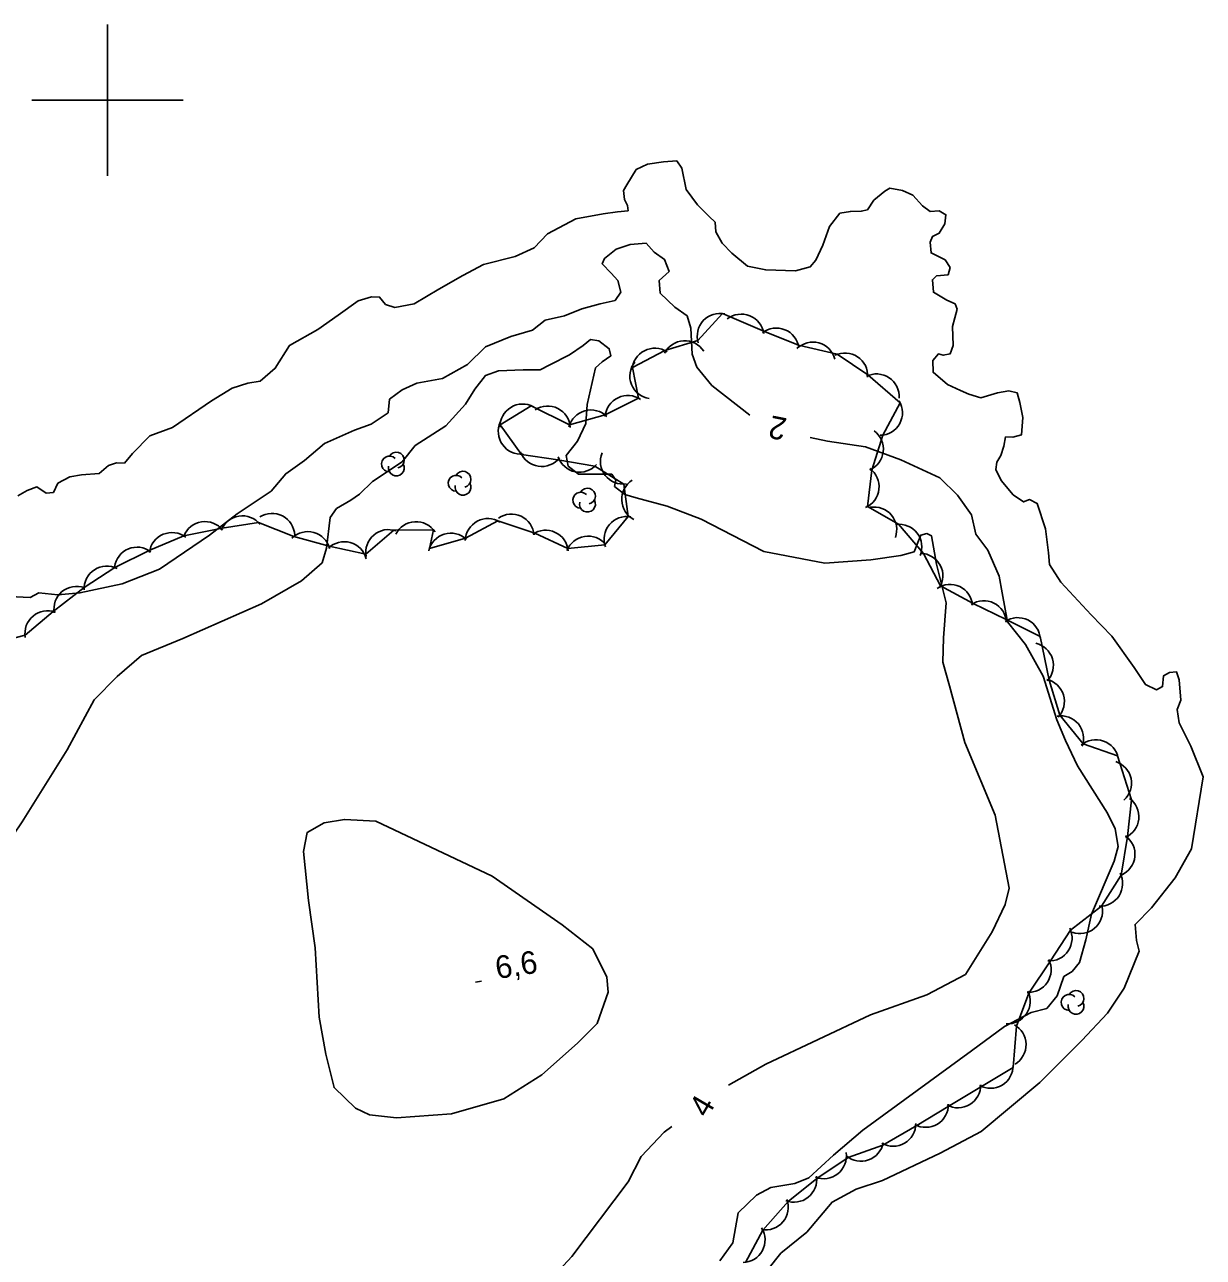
# Model space of a CAD drawing. Extents: x 643342 to 646936, y 5873857 to 5876103.
# Drawn here: x 644389 to 644544.9, y 5874247 to 5874410 of the extents above; entities that cross this region are included whole.
import ezdxf

# ---------------------------------------------------------------- set-up
doc = ezdxf.new("R2010")
doc.units = 0
for name, color, linetype in [('Niveau 2', 7, 'Continuous'), ('Niveau 3', 7, 'Continuous'), ('Niveau 4', 7, 'Continuous'), ('Niveau 44', 7, 'Continuous'), ('Niveau 61', 7, 'Continuous')]:
    doc.layers.add(name, color=color, linetype=linetype)

msp = doc.modelspace()

# ---------------------------------------------------------------- linework, layer by layer
at = {"layer": 'Niveau 2'}
for points in [[(644387.02, 5874334.38), (644389.75, 5874334.26), (644390.89, 5874334.84), (644393.4, 5874334.58), (644396.34, 5874334.84), (644401.93, 5874336.03), (644406.86, 5874338), (644413.47, 5874342.5), (644417.14, 5874345.31), (644421.62, 5874348.31), (644423.56, 5874350.61), (644426.02, 5874352.37), (644428.67, 5874354.62), (644432.67, 5874356.39), (644434.86, 5874357.17), (644437.1, 5874358.68), (644437.3, 5874360.47), (644438.98, 5874361.69), (644440.92, 5874362.57), (644444.3, 5874363.22), (644447.58, 5874365.05), (644449.99, 5874367.39), (644453.31, 5874368.75), (644456.2, 5874369.59), (644457.87, 5874370.93), (644460.43, 5874371.5), (644462.72, 5874372.42), (644465.15, 5874373.1), (644467.13, 5874373.51), (644467.86, 5874374.64), (644467.5, 5874376.16), (644466.59, 5874377.15), (644465.42, 5874378.35), (644465.71, 5874379.09), (644467.27, 5874380.29), (644469.11, 5874380.93), (644471.23, 5874381.11), (644472.28, 5874379.9), (644473.66, 5874378.95), (644474.27, 5874377.34), (644472.95, 5874376.15), (644473.09, 5874374.5), (644475.02, 5874372.65), (644476.66, 5874371.49), (644477.15, 5874369.87), (644477.32, 5874366.44), (644477.94, 5874364.71), (644479.92, 5874362.27), (644484.94, 5874358.34)], [(644428.94, 5874340.77), (644429.42, 5874344.84), (644430.27, 5874345.99), (644432.19, 5874347.1), (644433.3, 5874347.91), (644435.05, 5874349.6), (644438.97, 5874352.19), (644440.68, 5874354.36), (644444.72, 5874356.96), (644447.32, 5874359.79), (644448.57, 5874361.8), (644449.96, 5874363.58), (644451.68, 5874364.2), (644454.98, 5874364.37), (644457.23, 5874364.33), (644458.47, 5874365.03), (644461.09, 5874366.32), (644462.88, 5874367.55), (644463.87, 5874368.34), (644464.95, 5874368.2), (644466.34, 5874367.13), (644466.54, 5874366.2), (644465.42, 5874365.39), (644464.54, 5874364.61), (644463.41, 5874359.77), (644463.27, 5874357.26), (644462.16, 5874354.92), (644460.67, 5874353.01), (644460.9, 5874351.61), (644462.29, 5874350.54), (644466.67, 5874350.57), (644467.21, 5874349.78), (644467.04, 5874348.94), (644468.43, 5874347.87), (644469.89, 5874347.41), (644474, 5874346.34), (644478.52, 5874344.6), (644486.8, 5874340.34), (644494.85, 5874338.79), (644500.96, 5874339.2), (644504.93, 5874339.78), (644506.66, 5874340.29), (644507.15, 5874341.52), (644507.54, 5874342.5), (644508.36, 5874342.69), (644508.97, 5874342.39), (644509.64, 5874338.65), (644510.89, 5874333.55), (644510.57, 5874328.9), (644510.48, 5874325.7)], [(644492.92, 5874355.42), (644495.22, 5874354.93), (644500.26, 5874354.18), (644504.9, 5874352.45), (644510.07, 5874350.05), (644512.4, 5874347.76), (644514.27, 5874345.19), (644514.84, 5874342.63), (644516.44, 5874340.51), (644517.91, 5874337.08), (644518.33, 5874334.86), (644519, 5874331.01), (644521.38, 5874328.01), (644523.75, 5874323.83), (644525.53, 5874318.05), (644526.7, 5874315.31), (644528.28, 5874312), (644532.24, 5874305.71), (644533.24, 5874303.66), (644533.67, 5874301.33), (644533.12, 5874299.38), (644530.15, 5874292.37), (644529.37, 5874288.98), (644528.56, 5874285.95), (644527.59, 5874284.8), (644526.47, 5874284.11), (644525.61, 5874281.55), (644524.21, 5874279.88), (644522.13, 5874279.35), (644518.62, 5874277.5), (644514.27, 5874274.28), (644499.89, 5874263.79), (644496.02, 5874260.49), (644492.73, 5874257.48), (644490.9, 5874256.72), (644487.74, 5874256.21), (644485.82, 5874255.22), (644483.41, 5874252.87), (644482.68, 5874248.9), (644480.99, 5874246.5)], [(644325.11, 5874240.44), (644333.62, 5874247.45), (644341.01, 5874253.66), (644347.4, 5874260.49), (644360.4, 5874271.68), (644375.22, 5874286.59), (644382.72, 5874295.76), (644388.71, 5874304.58), (644394.65, 5874314.1), (644398.23, 5874320.69), (644401.28, 5874323.8), (644404.47, 5874326.56), (644409.96, 5874328.82), (644420.34, 5874333.39), (644425.64, 5874336.46), (644428.39, 5874338.83), (644428.94, 5874340.77)], [(644510.48, 5874325.7), (644511.34, 5874322.57), (644513.38, 5874315.05), (644517.37, 5874305.45), (644519.24, 5874295.79), (644518.72, 5874293.62), (644517.01, 5874290.03), (644513.46, 5874284.4), (644508.37, 5874281.71), (644500.91, 5874279.05), (644487.05, 5874272.52), (644482.14, 5874269.75)], [(644428.88, 5874273.83), (644427.99, 5874278.72), (644427.46, 5874287.89), (644426.57, 5874294.19), (644425.91, 5874300.64), (644426.4, 5874303.17), (644428.66, 5874304.43), (644431.33, 5874304.89), (644435.48, 5874304.66), (644450.85, 5874297.37), (644460.13, 5874290.96), (644464.17, 5874287.77), (644466.02, 5874284.03), (644466.19, 5874282.04), (644464.76, 5874277.9), (644462.15, 5874275.3), (644457.43, 5874271.11), (644452.39, 5874267.96), (644445.48, 5874265.94), (644438.2, 5874265.42), (644434.63, 5874265.82), (644432.78, 5874266.72), (644429.96, 5874269.43), (644428.88, 5874273.83)], [(644474.63, 5874264.29), (644473.62, 5874263.54), (644470.58, 5874260.32), (644468.86, 5874256.98), (644461.42, 5874247.1), (644449.83, 5874234.62)]]:
    msp.add_lwpolyline(points, dxfattribs=at)
at = {"layer": 'Niveau 3'}
msp.add_line((644448.67, 5874283.36), (644449.46, 5874283.48), dxfattribs=at)
at = {"layer": 'Niveau 4'}
for points in [[(644503.45, 5874388.38), (644502.78, 5874387.97), (644501.34, 5874386.77), (644500.49, 5874385.51), (644499.68, 5874385.32), (644498.25, 5874385.31), (644496.85, 5874385.07), (644495.46, 5874383.29), (644494.6, 5874380.83), (644493.69, 5874378.85), (644492.94, 5874377.96), (644490.97, 5874377.43), (644487.04, 5874377.56), (644484.63, 5874378.07), (644482.58, 5874379.79), (644481.29, 5874381.11), (644480.45, 5874382.58), (644480.34, 5874383.88), (644479.57, 5874384.65), (644478.02, 5874386.18), (644476.54, 5874388.19), (644475.95, 5874391), (644475.27, 5874392.01), (644473.51, 5874391.85), (644471.4, 5874391.55), (644469.91, 5874390.83), (644468.66, 5874388.82), (644468.25, 5874388.07), (644468.35, 5874386.89), (644468.77, 5874386.09), (644468.83, 5874385.38), (644467.42, 5874385.26), (644465.54, 5874384.98), (644461.92, 5874384.31), (644458.17, 5874382.32), (644456.42, 5874380.5), (644453.91, 5874379.33), (644449.73, 5874378.26), (644447, 5874376.83), (644443.83, 5874375.01), (644440.56, 5874373.06), (644437.99, 5874372.6), (644436.77, 5874372.97), (644435.97, 5874373.97), (644434.9, 5874374), (644433.16, 5874373.49), (644430.48, 5874371.59), (644427.79, 5874369.69), (644424.05, 5874367.58), (644422.17, 5874364.57), (644420.18, 5874362.85), (644418.54, 5874362.59), (644416.46, 5874361.93), (644413.75, 5874360.27), (644408.59, 5874356.73), (644405.6, 5874355.64), (644403.31, 5874353.3), (644402.23, 5874352.02), (644401.16, 5874352.04), (644400.12, 5874351.71), (644398.9, 5874350.66), (644396.55, 5874350.45), (644395.02, 5874350.2), (644393.43, 5874349.35), (644392.83, 5874348.11)], [(644541.45, 5874319.42), (644541.94, 5874320.65), (644541.72, 5874323.36), (644541.39, 5874324.4), (644540.45, 5874324.32), (644539.66, 5874323.9), (644539.54, 5874322.46), (644538.74, 5874322.03), (644537.26, 5874322.74), (644535.77, 5874324.98), (644532.82, 5874329.12), (644530.1, 5874331.97), (644526.06, 5874336.26), (644524.56, 5874338.62), (644524.44, 5874340.15), (644524.05, 5874343.33), (644522.94, 5874346.68), (644521.95, 5874347.19), (644521.15, 5874346.88), (644519.77, 5874347.83), (644518.19, 5874349.71), (644517.47, 5874351.19), (644517.63, 5874352.16), (644518.15, 5874353.04), (644518.52, 5874354.26), (644518.77, 5874355.47), (644519.72, 5874355.43), (644520.88, 5874355.77), (644521.05, 5874358.04), (644520.65, 5874360.03), (644520.3, 5874361.3), (644519.21, 5874361.57), (644517.69, 5874361.32), (644515.49, 5874360.65), (644513.92, 5874361.11), (644512.81, 5874361.61), (644511.08, 5874362.41), (644509.17, 5874364.02), (644509.16, 5874365.57), (644509.91, 5874366.47), (644510.52, 5874366.28), (644511.45, 5874366.48), (644511.83, 5874367.58), (644511.74, 5874370.07), (644512.38, 5874372.39), (644512.09, 5874373.08), (644510.98, 5874373.57), (644509.23, 5874374.61), (644509.09, 5874376.26), (644509.64, 5874376.79), (644511.17, 5874376.92), (644511.45, 5874377.9), (644510.77, 5874378.91), (644508.91, 5874379.82), (644508.8, 5874381.23), (644509.09, 5874381.97), (644510, 5874382.41), (644510.73, 5874383.66), (644510.87, 5874384.86), (644509.99, 5874385.38), (644508.81, 5874385.28), (644507.8, 5874386.02), (644506.5, 5874387.46), (644505.14, 5874388.05), (644503.45, 5874388.38)], [(644392.83, 5874348.11), (644391.89, 5874348.03), (644390.63, 5874348.87), (644389.36, 5874348.4), (644388.12, 5874347.7)], [(644487.34, 5874245.37), (644489.05, 5874247.53), (644492.49, 5874250.32), (644495.83, 5874254.29), (644499.01, 5874255.99), (644502.47, 5874257.12), (644510.1, 5874260.75), (644515.55, 5874263.6), (644523.3, 5874270.09), (644528.87, 5874275.67), (644532.24, 5874279.29), (644534.46, 5874282.57), (644536.42, 5874287.48), (644536.06, 5874288.88), (644535.89, 5874291), (644538.07, 5874293.2), (644541.18, 5874297.15), (644543.34, 5874301.02), (644544.92, 5874310.54), (644543.27, 5874314.59), (644541.72, 5874317.66), (644541.45, 5874319.42)]]:
    msp.add_lwpolyline(points, dxfattribs=at)
at = {"layer": 'Niveau 44'}
for points in [[(644484.36, 5874246.31), (644486.64, 5874250.59), (644489.99, 5874254.38), (644493.79, 5874257.4), (644497.94, 5874260.2), (644502.51, 5874261.83), (644507.03, 5874264.41), (644511.18, 5874266.91), (644515.59, 5874269.57), (644519.75, 5874272.07), (644520.2, 5874277.56), (644521.84, 5874281.9), (644524.69, 5874286.18), (644527.37, 5874290.23), (644531.44, 5874293.42), (644534.04, 5874297.52), (644534.91, 5874302.65), (644535.41, 5874307.48), (644533.59, 5874313.29), (644529.01, 5874314.89), (644525.94, 5874318.67), (644524.53, 5874323.32), (644523.33, 5874329.08), (644518.85, 5874331.31), (644514.5, 5874333.46), (644510.18, 5874335.78), (644507.89, 5874340.06), (644504.61, 5874343.92), (644500.52, 5874346.28), (644501.06, 5874351.1), (644502.51, 5874355.72), (644504.84, 5874359.97), (644500.53, 5874363.71), (644496.49, 5874366.4), (644491.37, 5874367.62), (644486.86, 5874369.41), (644481.34, 5874371.8), (644478.05, 5874368.23), (644473.72, 5874366.89), (644469.41, 5874364.67), (644470.23, 5874360.6), (644465.79, 5874358.39), (644461.11, 5874357.09), (644456.04, 5874359.6), (644451.91, 5874357.06), (644454.75, 5874353.17), (644459.55, 5874352.46), (644464.46, 5874351.61), (644468.29, 5874349.24), (644468.87, 5874344.94), (644465.75, 5874341.22), (644460.88, 5874340.7), (644456.49, 5874342.77), (644451.61, 5874344.38), (644447.32, 5874342.1), (644442.56, 5874340.73), (644443.12, 5874343.17)], [(644443.12, 5874343.17), (644437.84, 5874343.14), (644434.15, 5874339.98), (644429.29, 5874341.01), (644424.61, 5874342.3), (644419.95, 5874344.16), (644415.16, 5874343.42), (644410.07, 5874342.39), (644405.59, 5874340.52), (644400.97, 5874338.19), (644396.9, 5874335.55), (644392.79, 5874332.41), (644389.08, 5874329.28), (644384.1, 5874327.99)]]:
    msp.add_lwpolyline(points, dxfattribs=at)
for centre, radius, start, end in [((644480.99, 5874368.82), 3, 77.3341, 197.312), ((644480.99, 5874368.82), 3, 77.3341, 197.312), ((644480.99, 5874368.82), 3, 77.3341, 197.312), ((644483.82, 5874368.72), 3, 8.3251, 128.303), ((644483.82, 5874368.72), 3, 8.3251, 128.303), ((644483.82, 5874368.72), 3, 8.3251, 128.303), ((644488.46, 5874366.87), 3, 8.3251, 128.303), ((644488.46, 5874366.87), 3, 8.3251, 128.303), ((644488.46, 5874366.87), 3, 8.3251, 128.303), ((644476.33, 5874365.19), 3, 33.0632, 153.0411), ((644476.33, 5874365.19), 3, 33.0632, 153.0411), ((644476.33, 5874365.19), 3, 33.0632, 153.0411), ((644493.28, 5874365.02), 3, 14.538, 134.5159), ((644493.28, 5874365.02), 3, 14.538, 134.5159), ((644493.28, 5874365.02), 3, 14.538, 134.5159), ((644472.37, 5874364.21), 3, 57.1839, 177.1619), ((644472.37, 5874364.21), 3, 57.1839, 177.1619), ((644472.37, 5874364.21), 3, 57.1839, 177.1619), ((644497.53, 5874363.58), 3, 356.3292, 116.3072), ((644497.53, 5874363.58), 3, 356.3292, 116.3072), ((644497.53, 5874363.58), 3, 356.3292, 116.3072), ((644472.07, 5874363.52), 3, 141.7254, 261.7034), ((644472.07, 5874363.52), 3, 141.7254, 261.7034), ((644472.07, 5874363.52), 3, 141.7254, 261.7034), ((644501.69, 5874360.81), 3, 356.3292, 116.3072), ((644501.69, 5874360.81), 3, 356.3292, 116.3072), ((644501.69, 5874360.81), 3, 356.3292, 116.3072), ((644454.9, 5874356.83), 3, 61.5602, 181.5381), ((644454.9, 5874356.83), 3, 61.5602, 181.5381), ((644454.9, 5874356.83), 3, 61.5602, 181.5381), ((644458.2, 5874356.56), 3, 3.2752, 123.2532), ((644458.2, 5874356.56), 3, 3.2752, 123.2532), ((644458.2, 5874356.56), 3, 3.2752, 123.2532), ((644468.8, 5874357.96), 3, 55.5543, 175.5323), ((644468.8, 5874357.96), 3, 55.5543, 175.5323), ((644468.8, 5874357.96), 3, 55.5543, 175.5323), ((644502.13, 5874358.69), 3, 271.2217, 31.1997), ((644502.13, 5874358.69), 3, 271.2217, 31.1997), ((644502.13, 5874358.69), 3, 271.2217, 31.1997), ((644463.92, 5874356.04), 3, 45.435, 165.413), ((644463.92, 5874356.04), 3, 45.435, 165.413), ((644463.92, 5874356.04), 3, 45.435, 165.413), ((644454.67, 5874356.2), 3, 155.5814, 275.5594), ((644454.67, 5874356.2), 3, 155.5814, 275.5594), ((644454.67, 5874356.2), 3, 155.5814, 275.5594), ((644499.6, 5874353.85), 3, 293.519, 53.4969), ((644499.6, 5874353.85), 3, 293.519, 53.4969), ((644499.6, 5874353.85), 3, 293.519, 53.4969), ((644437.28, 5874351.89), 1.05, 44.1154, 269.804), ((644438.18, 5874352.42), 1.05, 282.2692, 149.7263), ((644457.4, 5874354.56), 3, 201.6462, 321.6241), ((644457.4, 5874354.56), 3, 201.6462, 321.6241), ((644457.4, 5874354.56), 3, 201.6462, 321.6241), ((644468.18, 5874352.24), 3, 158.0467, 278.0246), ((644468.18, 5874352.24), 3, 158.0467, 278.0246), ((644468.18, 5874352.24), 3, 158.0467, 278.0246), ((644438.18, 5874351.37), 1.05, 166.9369, 29.6212), ((644462.42, 5874353.81), 3, 198.9911, 318.9691), ((644462.42, 5874353.81), 3, 198.9911, 318.9691), ((644462.42, 5874353.81), 3, 198.9911, 318.9691), ((644499.04, 5874348.89), 3, 293.519, 53.4969), ((644499.04, 5874348.89), 3, 293.519, 53.4969), ((644499.04, 5874348.89), 3, 293.519, 53.4969), ((644446.11, 5874349.35), 1.05, 44.1154, 269.804), ((644447.01, 5874349.88), 1.05, 282.2692, 149.7263), ((644470.99, 5874347.22), 3, 122.4386, 242.4165), ((644470.99, 5874347.22), 3, 122.4386, 242.4165), ((644470.99, 5874347.22), 3, 122.4386, 242.4165), ((644447.01, 5874348.83), 1.05, 166.9369, 29.6212), ((644462.57, 5874347.11), 1.05, 44.1154, 269.804), ((644463.47, 5874347.64), 1.05, 282.2692, 149.7263), ((644463.47, 5874346.59), 1.05, 166.9369, 29.6212), ((644417.82, 5874342.04), 3, 38.8022, 158.7801), ((644417.82, 5874342.04), 3, 38.8022, 158.7801), ((644417.82, 5874342.04), 3, 38.8022, 158.7801), ((644421.75, 5874342.36), 3, 2.6257, 122.6036), ((644421.75, 5874342.36), 3, 2.6257, 122.6036), ((644421.75, 5874342.36), 3, 2.6257, 122.6036), ((644453.41, 5874342.27), 3, 4.7875, 124.7654), ((644453.41, 5874342.27), 3, 4.7875, 124.7654), ((644453.41, 5874342.27), 3, 4.7875, 124.7654), ((644468.66, 5874341.95), 3, 79.9675, 199.9455), ((644468.66, 5874341.95), 3, 79.9675, 199.9455), ((644468.66, 5874341.95), 3, 79.9675, 199.9455), ((644501.37, 5874343.21), 3, 339.9245, 99.9024), ((644501.37, 5874343.21), 3, 339.9245, 99.9024), ((644501.37, 5874343.21), 3, 339.9245, 99.9024), ((644412.88, 5874341.28), 3, 38.8022, 158.7801), ((644412.88, 5874341.28), 3, 38.8022, 158.7801), ((644412.88, 5874341.28), 3, 38.8022, 158.7801), ((644437.14, 5874340.22), 3, 70.5211, 190.499), ((644437.14, 5874340.22), 3, 70.5211, 190.499), ((644437.14, 5874340.22), 3, 70.5211, 190.499), ((644440.8, 5874341.27), 3, 33.3406, 153.3185), ((644440.8, 5874341.27), 3, 33.3406, 153.3185), ((644440.8, 5874341.27), 3, 33.3406, 153.3185), ((644450.3, 5874341.68), 3, 58.0219, 177.9999), ((644450.3, 5874341.68), 3, 58.0219, 177.9999), ((644450.3, 5874341.68), 3, 58.0219, 177.9999), ((644457.93, 5874340.14), 3, 4.7875, 124.7654), ((644457.93, 5874340.14), 3, 4.7875, 124.7654), ((644457.93, 5874340.14), 3, 4.7875, 124.7654), ((644504.69, 5874340.92), 3, 337.6282, 97.6061), ((644504.69, 5874340.92), 3, 337.6282, 97.6061), ((644504.69, 5874340.92), 3, 337.6282, 97.6061), ((644408.51, 5874339.83), 3, 52.7144, 172.6923), ((644408.51, 5874339.83), 3, 52.7144, 172.6923), ((644408.51, 5874339.83), 3, 52.7144, 172.6923), ((644426.48, 5874339.95), 3, 14.5191, 134.497), ((644426.48, 5874339.95), 3, 14.5191, 134.497), ((644426.48, 5874339.95), 3, 14.5191, 134.497), ((644431.3, 5874338.62), 3, 14.5191, 134.497), ((644431.3, 5874338.62), 3, 14.5191, 134.497), ((644431.3, 5874338.62), 3, 14.5191, 134.497), ((644445.4, 5874339.75), 3, 46.9723, 166.9502), ((644445.4, 5874339.75), 3, 46.9723, 166.9502), ((644445.4, 5874339.75), 3, 46.9723, 166.9502), ((644463.54, 5874339.36), 3, 38.7189, 158.6968), ((644463.54, 5874339.36), 3, 38.7189, 158.6968), ((644463.54, 5874339.36), 3, 38.7189, 158.6968), ((644403.9, 5874337.9), 3, 52.7144, 172.6923), ((644403.9, 5874337.9), 3, 52.7144, 172.6923), ((644403.9, 5874337.9), 3, 52.7144, 172.6923), ((644507.48, 5874337.08), 3, 328.2128, 88.1908), ((644507.48, 5874337.08), 3, 328.2128, 88.1908), ((644507.48, 5874337.08), 3, 328.2128, 88.1908), ((644399.89, 5874335.39), 3, 62.9332, 182.9112), ((644399.89, 5874335.39), 3, 62.9332, 182.9112), ((644399.89, 5874335.39), 3, 62.9332, 182.9112), ((644395.9, 5874332.72), 3, 70.1551, 190.1331), ((644395.9, 5874332.72), 3, 70.1551, 190.1331), ((644395.9, 5874332.72), 3, 70.1551, 190.1331), ((644511.41, 5874332.97), 3, 4.5429, 124.5209), ((644511.41, 5874332.97), 3, 4.5429, 124.5209), ((644511.41, 5874332.97), 3, 4.5429, 124.5209), ((644515.89, 5874330.81), 3, 3.5897, 123.5677), ((644515.89, 5874330.81), 3, 3.5897, 123.5677), ((644515.89, 5874330.81), 3, 3.5897, 123.5677), ((644392.07, 5874329.5), 3, 70.1551, 190.1331), ((644392.07, 5874329.5), 3, 70.1551, 190.1331), ((644392.07, 5874329.5), 3, 70.1551, 190.1331), ((644520.37, 5874328.58), 3, 3.5897, 123.5677), ((644520.37, 5874328.58), 3, 3.5897, 123.5677), ((644520.37, 5874328.58), 3, 3.5897, 123.5677), ((644522.09, 5874325.26), 3, 316.9285, 76.9064), ((644522.09, 5874325.26), 3, 316.9285, 76.9064), ((644522.09, 5874325.26), 3, 316.9285, 76.9064), ((644523.55, 5874320.48), 3, 316.9285, 76.9064), ((644523.55, 5874320.48), 3, 316.9285, 76.9064), ((644523.55, 5874320.48), 3, 316.9285, 76.9064), ((644526.08, 5874315.6), 3, 339.6785, 99.6564), ((644526.08, 5874315.6), 3, 339.6785, 99.6564), ((644526.08, 5874315.6), 3, 339.6785, 99.6564), ((644530.72, 5874312.43), 3, 10.7699, 130.7478), ((644530.72, 5874312.43), 3, 10.7699, 130.7478), ((644530.72, 5874312.43), 3, 10.7699, 130.7478), ((644532.42, 5874309.68), 3, 311.8972, 71.8752), ((644532.42, 5874309.68), 3, 311.8972, 71.8752), ((644532.42, 5874309.68), 3, 311.8972, 71.8752), ((644533.4, 5874305.25), 3, 294.0664, 54.0443), ((644533.4, 5874305.25), 3, 294.0664, 54.0443), ((644533.4, 5874305.25), 3, 294.0664, 54.0443), ((644532.88, 5874300.28), 3, 294.0664, 54.0443), ((644532.88, 5874300.28), 3, 294.0664, 54.0443), ((644532.88, 5874300.28), 3, 294.0664, 54.0443), ((644531.25, 5874296.41), 3, 267.6347, 27.6127), ((644531.25, 5874296.41), 3, 267.6347, 27.6127), ((644531.25, 5874296.41), 3, 267.6347, 27.6127), ((644528.59, 5874292.79), 3, 250.2345, 10.2124), ((644528.59, 5874292.79), 3, 250.2345, 10.2124), ((644528.59, 5874292.79), 3, 250.2345, 10.2124), ((644524.56, 5874289.18), 3, 266.4378, 26.4157), ((644524.56, 5874289.18), 3, 266.4378, 26.4157), ((644524.56, 5874289.18), 3, 266.4378, 26.4157), ((644521.79, 5874285.01), 3, 266.4378, 26.4157), ((644521.79, 5874285.01), 3, 266.4378, 26.4157), ((644521.79, 5874285.01), 3, 266.4378, 26.4157), ((644519.03, 5874280.85), 3, 266.4378, 26.4157), ((644519.03, 5874280.85), 3, 266.4378, 26.4157), ((644519.03, 5874280.85), 3, 266.4378, 26.4157), ((644527.18, 5874280.69), 1.05, 44.1154, 269.804), ((644528.08, 5874281.22), 1.05, 282.2692, 149.7263), ((644528.08, 5874280.17), 1.05, 166.9369, 29.6212), ((644518.48, 5874275.11), 3, 300.9848, 60.9627), ((644518.48, 5874275.11), 3, 300.9848, 60.9627), ((644518.48, 5874275.11), 3, 300.9848, 60.9627), ((644516.76, 5874272.33), 3, 241.0585, 1.0364), ((644516.76, 5874272.33), 3, 241.0585, 1.0364), ((644516.76, 5874272.33), 3, 241.0585, 1.0364), ((644512.48, 5874269.75), 3, 241.0585, 1.0364), ((644512.48, 5874269.75), 3, 241.0585, 1.0364), ((644512.48, 5874269.75), 3, 241.0585, 1.0364), ((644508.2, 5874267.17), 3, 241.0585, 1.0364), ((644508.2, 5874267.17), 3, 241.0585, 1.0364), ((644508.2, 5874267.17), 3, 241.0585, 1.0364), ((644503.9, 5874264.66), 3, 240.0686, 0.0466), ((644503.9, 5874264.66), 3, 240.0686, 0.0466), ((644503.9, 5874264.66), 3, 240.0686, 0.0466), ((644499.64, 5874262.68), 3, 229.5719, 349.5498), ((644499.64, 5874262.68), 3, 229.5719, 349.5498), ((644499.64, 5874262.68), 3, 229.5719, 349.5498), ((644494.71, 5874260.38), 3, 248.4426, 8.4205), ((644494.71, 5874260.38), 3, 248.4426, 8.4205), ((644494.71, 5874260.38), 3, 248.4426, 8.4205), ((644490.79, 5874257.27), 3, 248.4426, 8.4205), ((644490.79, 5874257.27), 3, 248.4426, 8.4205), ((644490.79, 5874257.27), 3, 248.4426, 8.4205), ((644487.02, 5874253.59), 3, 259.9326, 19.9106), ((644487.02, 5874253.59), 3, 259.9326, 19.9106), ((644487.02, 5874253.59), 3, 259.9326, 19.9106), ((644483.95, 5874249.28), 3, 271.9435, 31.9215), ((644483.95, 5874249.28), 3, 271.9435, 31.9215), ((644483.95, 5874249.28), 3, 271.9435, 31.9215)]:
    msp.add_arc(centre, radius, start, end, dxfattribs=at)
at = {"layer": 'Niveau 61'}
for points in [[(644400, 5874410), (644400, 5874400), (644400, 5874390)], [(644390, 5874400), (644400, 5874400), (644410, 5874400)]]:
    msp.add_lwpolyline(points, dxfattribs=at)

# ---------------------------------------------------------------- texts
at = {"layer": 'Niveau 2'}
for s, rotation, p in [('2', 169.0075, (644489.99, 5874357.91)), ('4', 59.6535, (644479.32, 5874265.3))]:
    msp.add_text(s, height=3, rotation=rotation, dxfattribs=at).set_placement(p)
at = {"layer": 'Niveau 3'}
msp.add_text('6,6  ', height=3, rotation=8.9405, dxfattribs=at).set_placement((644451.52, 5874283.77))

doc.saveas('drawing.dxf')
